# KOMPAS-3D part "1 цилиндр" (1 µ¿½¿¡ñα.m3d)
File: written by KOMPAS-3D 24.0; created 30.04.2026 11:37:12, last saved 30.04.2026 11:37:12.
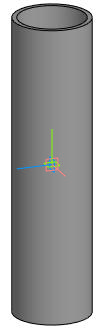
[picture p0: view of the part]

Document properties: Автор: USG_411; Полное имя файла: C:\Users\USG_411\Desktop\ИА-2904_411-12\Балка\1 цилиндр.m3d

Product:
- Part/product: 1 цилиндр
    Масса: 187.570674

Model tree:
1. Эскиз:1
2. Элемент выдавливания:1
     Расстояние 1 = 1250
